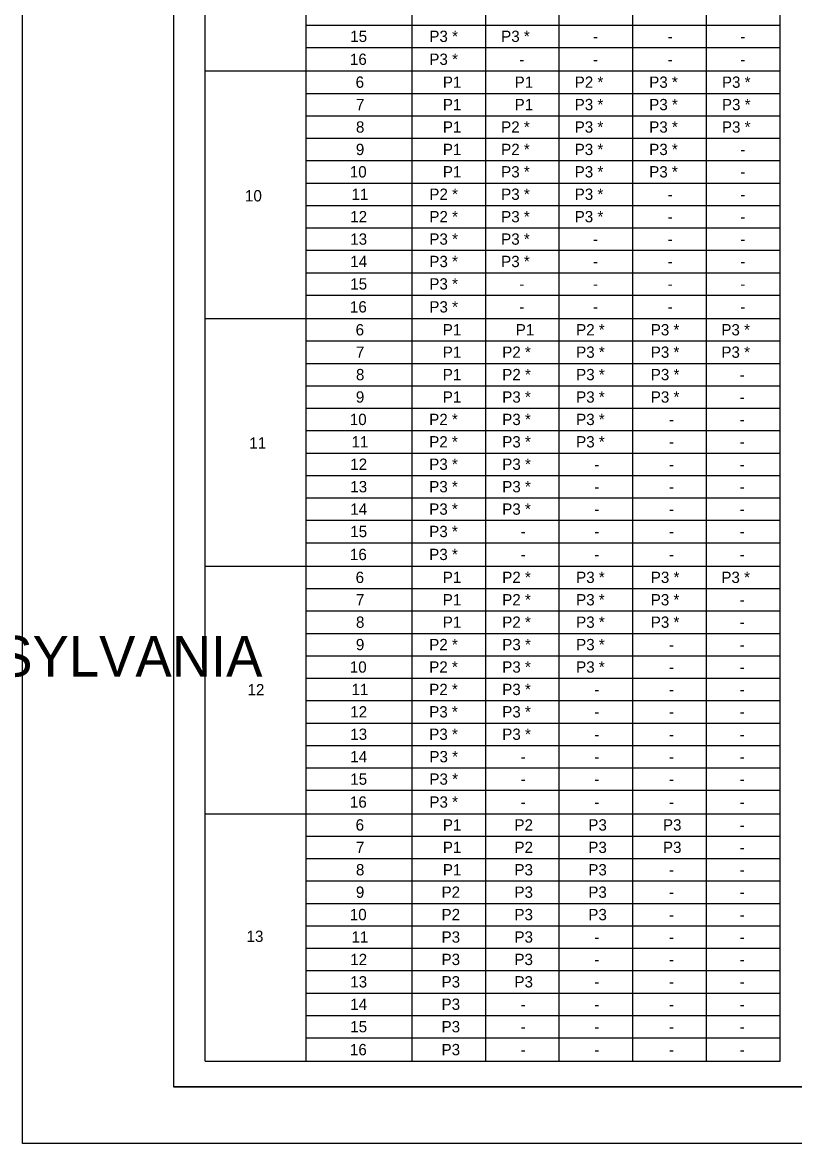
# Model space of a CAD drawing. Extents: x -2340 to 628, y -879 to 309.
# Drawn here: x -1117.4 to -912.9, y -878.6 to -581.5 of the extents above; entities that cross this region are included whole.
import ezdxf

# ---------------------------------------------------------------- set-up
doc = ezdxf.new("R2010")
doc.units = 0
for name, color, linetype in [('Level 1', 7, 'Continuous'), ('Level 2', 7, 'Continuous'), ('Level 30', 7, 'Continuous'), ('PLT-BNDY', 7, 'Continuous')]:
    doc.layers.add(name, color=color, linetype=linetype)

msp = doc.modelspace()

# ---------------------------------------------------------------- linework, layer by layer
at = {"layer": 'Level 1'}
for p, q in [((-1077.39, -299.56), (-1077.39, -863.56)), ((-1069, -856.76), (-1069, -331.88)), ((-916.65, -856.76), (-916.65, -331.88)), ((-1042.2, -665.87), (-916.65, -665.87)), ((-1042.2, -671.81), (-916.65, -671.81)), ((-1042.2, -677.75), (-916.65, -677.75)), ((-1042.2, -683.69), (-916.65, -683.69)), ((-1042.2, -689.63), (-916.65, -689.63)), ((-1042.2, -695.57), (-916.65, -695.57)), ((-1042.2, -701.51), (-916.65, -701.51)), ((-1042.2, -707.45), (-916.65, -707.45)), ((-1042.2, -713.39), (-916.65, -713.39)), ((-1042.2, -719.33), (-916.65, -719.33)), ((-1069, -725.54), (-916.65, -725.54)), ((-1042.2, -731.48), (-916.65, -731.48)), ((-1042.2, -737.42), (-916.65, -737.42)), ((-1042.2, -743.36), (-916.65, -743.36)), ((-1042.2, -749.3), (-916.65, -749.3)), ((-940.21, -749.3), (-916.65, -749.3)), ((-1042.2, -755.24), (-916.65, -755.24)), ((-1042.2, -761.18), (-916.65, -761.18)), ((-1042.2, -767.12), (-916.65, -767.12)), ((-940.21, -767.12), (-916.65, -767.12)), ((-1042.2, -773.06), (-916.65, -773.06)), ((-1042.2, -779), (-916.65, -779)), ((-1042.2, -784.94), (-916.65, -784.94)), ((-1069, -791.15), (-916.65, -791.15)), ((-1042.2, -797.09), (-916.65, -797.09)), ((-1042.2, -803.03), (-916.65, -803.03)), ((-1042.2, -808.97), (-916.65, -808.97)), ((-1042.2, -814.91), (-916.65, -814.91)), ((-1042.2, -820.85), (-916.65, -820.85)), ((-1042.2, -826.79), (-916.65, -826.79)), ((-1042.2, -832.73), (-916.65, -832.73)), ((-1042.2, -838.67), (-916.65, -838.67)), ((-1042.2, -844.61), (-916.65, -844.61)), ((-1042.2, -850.55), (-916.65, -850.55)), ((-1069, -856.76), (-916.65, -856.76)), ((-291.39, -863.56), (-1077.39, -863.56)), ((-1077.39, -863.56), (-491.39, -863.56))]:
    msp.add_line(p, q, dxfattribs=at)
at = {"layer": 'Level 2'}
for p, q in [((-1042.2, -856.76), (-1042.2, -331.88)), ((-1014.19, -856.76), (-1014.19, -331.88)), ((-994.68, -856.76), (-994.68, -331.88)), ((-975.17, -856.76), (-975.17, -331.88)), ((-955.67, -856.76), (-955.67, -331.88)), ((-936.16, -856.76), (-936.16, -331.88)), ((-1042.2, -582.17), (-916.65, -582.17)), ((-1042.2, -588.11), (-916.65, -588.11)), ((-1069, -594.32), (-916.65, -594.32)), ((-1042.2, -600.26), (-916.65, -600.26)), ((-1042.2, -606.2), (-916.65, -606.2)), ((-1042.2, -612.14), (-916.65, -612.14)), ((-1042.2, -618.08), (-916.65, -618.08)), ((-1042.2, -624.02), (-916.65, -624.02)), ((-1042.2, -629.96), (-916.65, -629.96)), ((-1042.2, -635.9), (-916.65, -635.9)), ((-1042.2, -641.84), (-916.65, -641.84)), ((-1042.2, -647.78), (-916.65, -647.78)), ((-1042.2, -653.72), (-916.65, -653.72)), ((-975.85, -653.72), (-940.21, -653.72)), ((-1069, -659.93), (-916.65, -659.93))]:
    msp.add_line(p, q, dxfattribs=at)
at = {"layer": 'PLT-BNDY'}
msp.add_lwpolyline([(-1117.39, -284.56), (-276.39, -284.56), (-276.39, -878.56), (-1117.39, -878.56)], close=True, dxfattribs=at)

# ---------------------------------------------------------------- texts
at = {"layer": 'Level 1'}
for s, height, p in [('P1', 3, (-1006.05, -670.34)), ('P2 *', 3, (-990.29, -670.34)), ('P3 *', 3, (-970.72, -670.34)), ('P3 *', 3, (-950.95, -670.34)), ('P3 *', 3, (-932.25, -670.34)), ('P1', 3, (-1006.05, -676.28)), ('P2 *', 3, (-990.29, -676.28)), ('P3 *', 3, (-970.72, -676.28)), ('P3 *', 3, (-950.95, -676.28)), ('-', 3, (-927.4, -676.28)), ('P1', 3, (-1006.05, -682.22)), ('P3 *', 3, (-990.29, -682.22)), ('P3 *', 3, (-970.72, -682.22)), ('P3 *', 3, (-950.95, -682.22)), ('-', 3, (-927.4, -682.22)), ('P2 *', 3, (-1009.63, -688.16)), ('P3 *', 3, (-990.29, -688.16)), ('P3 *', 3, (-970.72, -688.16)), ('-', 3, (-946.1, -688.16)), ('-', 3, (-927.4, -688.16)), ('P2 *', 3, (-1009.63, -694.1)), ('P3 *', 3, (-990.29, -694.1)), ('P3 *', 3, (-970.72, -694.1)), ('-', 3, (-946.1, -694.1)), ('-', 3, (-927.4, -694.1)), ('P3 *', 3, (-1009.63, -700.04)), ('P3 *', 3, (-990.29, -700.04)), ('-', 3, (-965.87, -700.04)), ('-', 3, (-946.1, -700.04)), ('-', 3, (-927.4, -700.04)), ('P3 *', 3, (-1009.63, -705.98)), ('P3 *', 3, (-990.29, -705.98)), ('-', 3, (-965.87, -705.98)), ('-', 3, (-946.1, -705.98)), ('-', 3, (-927.4, -705.98)), ('P3 *', 3, (-1009.63, -711.92)), ('P3 *', 3, (-990.29, -711.92)), ('-', 3, (-965.87, -711.92)), ('-', 3, (-946.1, -711.92)), ('-', 3, (-927.4, -711.92)), ('P3 *', 3, (-1009.63, -717.86)), ('-', 3, (-985.44, -717.86)), ('-', 3, (-965.87, -717.86)), ('-', 3, (-946.1, -717.86)), ('-', 3, (-927.4, -717.86)), ('P3 *', 3, (-1009.63, -723.94)), ('-', 3, (-985.44, -723.94)), ('-', 3, (-965.87, -723.94)), ('-', 3, (-946.1, -723.94)), ('-', 3, (-927.4, -723.94)), ('P1', 3, (-1006.05, -730.01)), ('P2 *', 3, (-990.29, -730.01)), ('P3 *', 3, (-970.72, -730.01)), ('P3 *', 3, (-950.95, -730.01)), ('P3 *', 3, (-932.25, -730.01)), ('P1', 3, (-1006.05, -735.95)), ('P2 *', 3, (-990.29, -735.95)), ('P3 *', 3, (-970.72, -735.95)), ('P3 *', 3, (-950.95, -735.95)), ('-', 3, (-927.4, -735.95)), ('P1', 3, (-1006.05, -741.89)), ('P2 *', 3, (-990.29, -741.89)), ('P3 *', 3, (-970.72, -741.89)), ('P3 *', 3, (-950.95, -741.89)), ('-', 3, (-927.4, -741.89)), ('COMMONWEALTH OF PENNSYLVANIA', 10.7827, (-1319.79, -754.83)), ('P2 *', 3, (-1009.63, -747.83)), ('P3 *', 3, (-990.29, -747.83)), ('P3 *', 3, (-970.72, -747.83)), ('-', 3, (-946.1, -747.83)), ('-', 3, (-927.4, -747.83)), ('P2 *', 3, (-1009.63, -753.77)), ('P3 *', 3, (-990.29, -753.77)), ('P3 *', 3, (-970.72, -753.77)), ('-', 3, (-946.1, -753.77)), ('-', 3, (-927.4, -753.77)), ('12', 3, (-1057.76, -759.79)), ('P2 *', 3, (-1009.63, -759.71)), ('P3 *', 3, (-990.29, -759.71)), ('-', 3, (-965.87, -759.71)), ('-', 3, (-946.1, -759.71)), ('-', 3, (-927.4, -759.71)), ('P3 *', 3, (-1009.63, -765.65)), ('P3 *', 3, (-990.29, -765.65)), ('-', 3, (-965.87, -765.65)), ('-', 3, (-946.1, -765.65)), ('-', 3, (-927.4, -765.65)), ('P3 *', 3, (-1009.63, -771.59)), ('P3 *', 3, (-990.29, -771.59)), ('-', 3, (-965.87, -771.59)), ('-', 3, (-946.1, -771.59)), ('-', 3, (-927.4, -771.59)), ('P3 *', 3, (-1009.59, -777.53)), ('-', 3, (-985.44, -777.53)), ('-', 3, (-965.87, -777.53)), ('-', 3, (-946.1, -777.53)), ('-', 3, (-927.4, -777.53)), ('P3 *', 3, (-1009.59, -783.47)), ('-', 3, (-985.44, -783.47)), ('-', 3, (-965.87, -783.47)), ('-', 3, (-946.1, -783.47)), ('-', 3, (-927.4, -783.47)), ('P3 *', 3, (-1009.59, -789.55)), ('-', 3, (-985.44, -789.55)), ('-', 3, (-965.87, -789.55)), ('-', 3, (-946.1, -789.55)), ('-', 3, (-927.4, -789.55)), ('P1', 3, (-1006.02, -795.62)), ('P2', 3, (-987.06, -795.62)), ('P3', 3, (-967.49, -795.62)), ('P3', 3, (-947.72, -795.62)), ('-', 3, (-927.4, -795.62)), ('P1', 3, (-1006.02, -801.56)), ('P2', 3, (-987.06, -801.56)), ('P3', 3, (-967.49, -801.56)), ('P3', 3, (-947.72, -801.56)), ('-', 3, (-927.4, -801.56)), ('P1', 3, (-1006.02, -807.5)), ('P3', 3, (-987.06, -807.5)), ('P3', 3, (-967.49, -807.5)), ('-', 3, (-946.1, -807.5)), ('-', 3, (-927.4, -807.5)), ('P2', 3, (-1006.36, -813.44)), ('P3', 3, (-987.06, -813.44)), ('P3', 3, (-967.49, -813.44)), ('-', 3, (-946.1, -813.44)), ('-', 3, (-927.4, -813.44)), ('P2', 3, (-1006.36, -819.38)), ('P3', 3, (-987.06, -819.38)), ('P3', 3, (-967.49, -819.38)), ('-', 3, (-946.1, -819.38)), ('-', 3, (-927.4, -819.38)), ('13', 3, (-1058.02, -825.13)), ('P3', 3, (-1006.36, -825.32)), ('P3', 3, (-987.06, -825.32)), ('-', 3, (-965.87, -825.32)), ('-', 3, (-946.1, -825.32)), ('-', 3, (-927.4, -825.32)), ('P3', 3, (-1006.36, -831.26)), ('P3', 3, (-987.06, -831.26)), ('-', 3, (-965.87, -831.26)), ('-', 3, (-946.1, -831.26)), ('-', 3, (-927.4, -831.26)), ('P3', 3, (-1006.36, -837.2)), ('P3', 3, (-987.06, -837.2)), ('-', 3, (-965.88, -837.2)), ('-', 3, (-946.1, -837.2)), ('-', 3, (-927.4, -837.2)), ('P3', 3, (-1006.36, -843.14)), ('-', 3, (-985.44, -843.14)), ('-', 3, (-965.88, -843.14)), ('-', 3, (-946.1, -843.14)), ('-', 3, (-927.4, -843.14)), ('P3', 3, (-1006.36, -849.08)), ('-', 3, (-985.44, -849.08)), ('-', 3, (-965.88, -849.08)), ('-', 3, (-946.1, -849.08)), ('-', 3, (-927.4, -849.08)), ('P3', 3, (-1006.36, -855.16)), ('-', 3, (-985.44, -855.16)), ('-', 3, (-965.88, -855.16)), ('-', 3, (-946.1, -855.16)), ('-', 3, (-927.4, -855.16))]:
    msp.add_text(s, height=height, dxfattribs=at).set_placement(p)
at = {"layer": 'Level 2'}
for s, p in [('15', (-1030.54, -586.64)), ('P3 *', (-1009.6, -586.64)), ('P3 *', (-990.58, -586.64)), ('-', (-966.25, -586.64)), ('-', (-946.51, -586.64)), ('-', (-927.25, -586.64)), ('16', (-1030.63, -592.72)), ('P3 *', (-1009.6, -592.72)), ('-', (-985.73, -592.72)), ('-', (-966.25, -592.72)), ('-', (-946.51, -592.72)), ('-', (-927.25, -592.72)), ('P1', (-1006.02, -598.79)), ('P1', (-987.01, -598.79)), ('P2 *', (-971.1, -598.79)), ('P3 *', (-951.36, -598.79)), ('P3 *', (-932.1, -598.79)), ('7', (-1029.04, -604.73)), ('P1', (-1006.02, -604.73)), ('P1', (-987.01, -604.73)), ('P3 *', (-971.1, -604.73)), ('P3 *', (-951.36, -604.73)), ('P3 *', (-932.1, -604.73)), ('8', (-1029.04, -610.67)), ('P1', (-1006.02, -610.67)), ('P2 *', (-990.58, -610.67)), ('P3 *', (-971.1, -610.67)), ('P3 *', (-951.36, -610.67)), ('P3 *', (-932.1, -610.67)), ('9', (-1029.06, -616.61)), ('P1', (-1006.02, -616.61)), ('P2 *', (-990.58, -616.61)), ('P3 *', (-971.1, -616.61)), ('P3 *', (-951.36, -616.61)), ('-', (-927.25, -616.61)), ('10', (-1030.67, -622.55)), ('P1', (-1006.02, -622.55)), ('P3 *', (-990.58, -622.55)), ('P3 *', (-971.1, -622.55)), ('P3 *', (-951.36, -622.55)), ('-', (-927.25, -622.55)), ('10', (-1058.43, -628.89)), ('11', (-1030.2, -628.49)), ('P2 *', (-1009.6, -628.49)), ('P3 *', (-990.58, -628.49)), ('P3 *', (-971.1, -628.49)), ('-', (-946.51, -628.49)), ('-', (-927.25, -628.49)), ('12', (-1030.54, -634.43)), ('P2 *', (-1009.6, -634.43)), ('P3 *', (-990.58, -634.43)), ('P3 *', (-971.1, -634.43)), ('-', (-946.51, -634.43)), ('-', (-927.25, -634.43)), ('13', (-1030.54, -640.37)), ('P3 *', (-1009.6, -640.37)), ('P3 *', (-990.58, -640.37)), ('-', (-966.25, -640.37)), ('-', (-946.51, -640.37)), ('-', (-927.25, -640.37)), ('14', (-1030.54, -646.31)), ('P3 *', (-1009.6, -646.31)), ('P3 *', (-990.58, -646.31)), ('-', (-966.25, -646.31)), ('-', (-946.51, -646.31)), ('-', (-927.25, -646.31)), ('15', (-1030.54, -652.25)), ('P3 *', (-1009.6, -652.25)), ('-', (-985.73, -652.25)), ('-', (-966.25, -652.25)), ('-', (-946.51, -652.25)), ('-', (-927.25, -652.25)), ('16', (-1030.63, -658.33)), ('P3 *', (-1009.6, -658.33)), ('-', (-985.73, -658.33)), ('-', (-966.25, -658.33)), ('-', (-946.51, -658.33)), ('-', (-927.25, -658.33)), ('7', (-1029.04, -670.34)), ('8', (-1029.04, -676.28)), ('9', (-1029.06, -682.22)), ('10', (-1030.67, -688.16)), ('11', (-1030.2, -694.1)), ('12', (-1030.54, -700.04)), ('13', (-1030.54, -705.98)), ('14', (-1030.54, -711.92)), ('15', (-1030.54, -717.86)), ('16', (-1030.63, -723.94)), ('7', (-1029.04, -735.95)), ('8', (-1029.04, -741.89)), ('9', (-1029.06, -747.83)), ('10', (-1030.67, -753.77)), ('11', (-1030.2, -759.71)), ('12', (-1030.54, -765.65)), ('13', (-1030.54, -771.59)), ('14', (-1030.54, -777.53)), ('15', (-1030.54, -783.47)), ('16', (-1030.63, -789.55)), ('7', (-1029.04, -801.56)), ('8', (-1029.04, -807.5)), ('9', (-1029.06, -813.44)), ('10', (-1030.67, -819.38)), ('11', (-1030.2, -825.32)), ('12', (-1030.54, -831.26)), ('13', (-1030.54, -837.2)), ('14', (-1030.54, -843.14)), ('15', (-1030.54, -849.08)), ('16', (-1030.63, -855.16))]:
    msp.add_text(s, height=3, dxfattribs=at).set_placement(p)
at = {"layer": 'Level 30'}
for s, p in [('6', (-1029.13, -598.79)), ('6', (-1029.13, -664.4)), ('P1', (-1006.05, -664.4)), ('P1', (-986.72, -664.4)), ('P2 *', (-970.72, -664.4)), ('P3 *', (-950.95, -664.4)), ('P3 *', (-932.25, -664.4)), ('11', (-1057.29, -694.42)), ('6', (-1029.13, -730.01)), ('6', (-1029.13, -795.62))]:
    msp.add_text(s, height=3, dxfattribs=at).set_placement(p)

doc.saveas('drawing.dxf')
